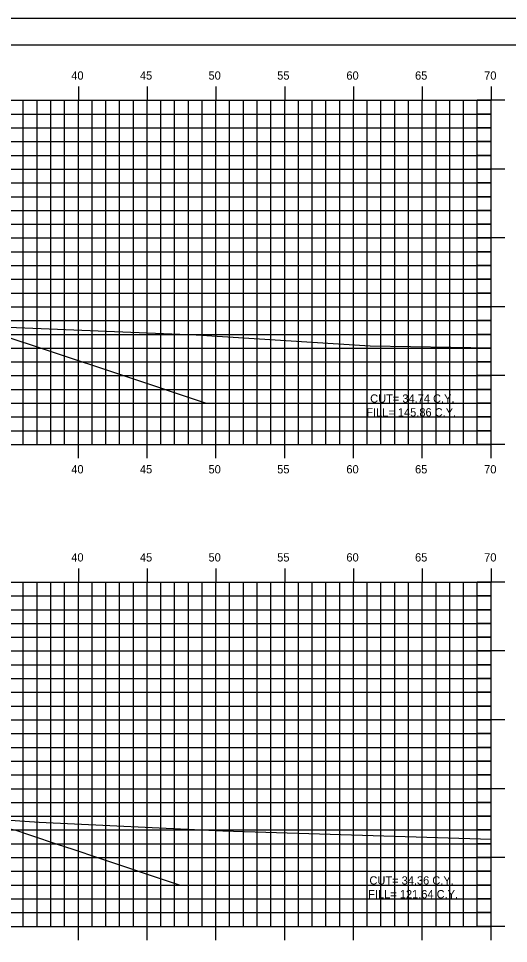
# Model space of a CAD drawing. Extents: x 1170543 to 1177585, y 609599 to 610623.
# Drawn here: x 1175836.2 to 1175871.9, y 609641.6 to 609708.8 of the extents above; entities that cross this region are included whole.
import ezdxf

# ---------------------------------------------------------------- set-up
doc = ezdxf.new("R2010")
doc.units = 0
for name, color, linetype in [('BORDER', 7, 'Continuous'), ('D_Roadway_Centerline_Text', 7, 'Continuous'), ('D_Roadway_Edge_Pavement', 7, 'Continuous'), ('H_V ANNOTATION', 7, 'Continuous'), ('MAJOR', 7, 'Continuous'), ('MINOR', 7, 'Continuous'), ('PLOT BOUNDARY', 7, 'Continuous'), ('S_Roadway_Centerline', 7, 'Continuous')]:
    doc.layers.add(name, color=color, linetype=linetype)

msp = doc.modelspace()

# ---------------------------------------------------------------- linework, layer by layer
at = {"layer": 'BORDER'}
msp.add_line((1175885.583, 609706.872), (1175725.583, 609706.872), dxfattribs=at)
at = {"layer": 'D_Roadway_Edge_Pavement'}
for points in [[(1175831.415, 609686.695), (1175834.869, 609685.872), (1175835.47, 609685.672), (1175837.87, 609684.872), (1175838.471, 609684.672), (1175840.872, 609683.872), (1175841.472, 609683.672), (1175843.874, 609682.872), (1175849.877, 609680.872), (1175870.583, 609680.872)], [(1175830.368, 609650.953), (1175835.978, 609649.872), (1175837.246, 609649.45), (1175838.981, 609648.872), (1175840.258, 609648.447), (1175841.984, 609647.872), (1175847.99, 609645.872), (1175870.583, 609645.872)]]:
    msp.add_lwpolyline(points, dxfattribs=at)
at = {"layer": 'MAJOR'}
for p, q in [((1175840.583, 609703.874), (1175840.583, 609702.872)), ((1175845.583, 609703.874), (1175845.583, 609702.872)), ((1175850.583, 609703.874), (1175850.583, 609702.872)), ((1175855.583, 609703.874), (1175855.583, 609702.872)), ((1175860.583, 609703.874), (1175860.583, 609702.872)), ((1175865.583, 609703.874), (1175865.583, 609702.872)), ((1175870.583, 609703.874), (1175870.583, 609702.872)), ((1175730.583, 609702.872), (1175870.583, 609702.872)), ((1175730.583, 609702.872), (1175870.583, 609702.872)), ((1175840.583, 609677.872), (1175840.583, 609702.872)), ((1175845.583, 609677.872), (1175845.583, 609702.872)), ((1175850.583, 609677.872), (1175850.583, 609702.872)), ((1175855.583, 609677.872), (1175855.583, 609702.872)), ((1175860.583, 609677.872), (1175860.583, 609702.872)), ((1175865.583, 609677.872), (1175865.583, 609702.872)), ((1175871.585, 609702.872), (1175869.581, 609702.872)), ((1175870.583, 609677.872), (1175870.583, 609702.872)), ((1175870.583, 609677.872), (1175870.583, 609702.872)), ((1175730.583, 609697.872), (1175870.583, 609697.872)), ((1175871.585, 609697.872), (1175869.581, 609697.872)), ((1175730.583, 609692.872), (1175870.583, 609692.872)), ((1175871.585, 609692.872), (1175869.581, 609692.872)), ((1175730.583, 609687.872), (1175870.583, 609687.872)), ((1175871.585, 609687.872), (1175869.581, 609687.872)), ((1175730.583, 609682.872), (1175870.583, 609682.872)), ((1175871.585, 609682.872), (1175869.581, 609682.872)), ((1175730.583, 609677.872), (1175870.583, 609677.872)), ((1175730.583, 609677.872), (1175870.583, 609677.872)), ((1175840.583, 609676.87), (1175840.583, 609677.872)), ((1175845.583, 609676.87), (1175845.583, 609677.872)), ((1175850.583, 609676.87), (1175850.583, 609677.872)), ((1175855.583, 609676.87), (1175855.583, 609677.872)), ((1175860.583, 609676.87), (1175860.583, 609677.872)), ((1175865.583, 609676.87), (1175865.583, 609677.872)), ((1175871.585, 609677.872), (1175869.581, 609677.872)), ((1175870.583, 609676.87), (1175870.583, 609677.872)), ((1175840.583, 609668.874), (1175840.583, 609667.872)), ((1175845.583, 609668.874), (1175845.583, 609667.872)), ((1175850.583, 609668.874), (1175850.583, 609667.872)), ((1175855.583, 609668.874), (1175855.583, 609667.872)), ((1175860.583, 609668.874), (1175860.583, 609667.872)), ((1175865.583, 609668.874), (1175865.583, 609667.872)), ((1175870.583, 609668.874), (1175870.583, 609667.872)), ((1175730.583, 609667.872), (1175870.583, 609667.872)), ((1175730.583, 609667.872), (1175870.583, 609667.872)), ((1175840.583, 609642.872), (1175840.583, 609667.872)), ((1175845.583, 609642.872), (1175845.583, 609667.872)), ((1175850.583, 609642.872), (1175850.583, 609667.872)), ((1175855.583, 609642.872), (1175855.583, 609667.872)), ((1175860.583, 609642.872), (1175860.583, 609667.872)), ((1175865.583, 609642.872), (1175865.583, 609667.872)), ((1175871.585, 609667.872), (1175869.581, 609667.872)), ((1175870.583, 609642.872), (1175870.583, 609667.872)), ((1175870.583, 609642.872), (1175870.583, 609667.872)), ((1175730.583, 609662.872), (1175870.583, 609662.872)), ((1175871.585, 609662.872), (1175869.581, 609662.872)), ((1175730.583, 609657.872), (1175870.583, 609657.872)), ((1175871.585, 609657.872), (1175869.581, 609657.872)), ((1175730.583, 609652.872), (1175870.583, 609652.872)), ((1175871.585, 609652.872), (1175869.581, 609652.872)), ((1175730.583, 609647.872), (1175870.583, 609647.872)), ((1175871.585, 609647.872), (1175869.581, 609647.872)), ((1175730.583, 609642.872), (1175870.583, 609642.872)), ((1175730.583, 609642.872), (1175870.583, 609642.872)), ((1175840.583, 609641.87), (1175840.583, 609642.872)), ((1175845.583, 609641.87), (1175845.583, 609642.872)), ((1175850.583, 609641.87), (1175850.583, 609642.872)), ((1175855.583, 609641.87), (1175855.583, 609642.872)), ((1175860.583, 609641.87), (1175860.583, 609642.872)), ((1175865.583, 609641.87), (1175865.583, 609642.872)), ((1175871.585, 609642.872), (1175869.581, 609642.872)), ((1175870.583, 609641.87), (1175870.583, 609642.872))]:
    msp.add_line(p, q, dxfattribs=at)
at = {"layer": 'MINOR'}
for p, q in [((1175836.583, 609677.872), (1175836.583, 609702.872)), ((1175837.583, 609677.872), (1175837.583, 609702.872)), ((1175838.583, 609677.872), (1175838.583, 609702.872)), ((1175839.583, 609677.872), (1175839.583, 609702.872)), ((1175841.583, 609677.872), (1175841.583, 609702.872)), ((1175842.583, 609677.872), (1175842.583, 609702.872)), ((1175843.583, 609677.872), (1175843.583, 609702.872)), ((1175844.583, 609677.872), (1175844.583, 609702.872)), ((1175846.583, 609677.872), (1175846.583, 609702.872)), ((1175847.583, 609677.872), (1175847.583, 609702.872)), ((1175848.583, 609677.872), (1175848.583, 609702.872)), ((1175849.583, 609677.872), (1175849.583, 609702.872)), ((1175851.583, 609677.872), (1175851.583, 609702.872)), ((1175852.583, 609677.872), (1175852.583, 609702.872)), ((1175853.583, 609677.872), (1175853.583, 609702.872)), ((1175854.583, 609677.872), (1175854.583, 609702.872)), ((1175856.583, 609677.872), (1175856.583, 609702.872)), ((1175857.583, 609677.872), (1175857.583, 609702.872)), ((1175858.583, 609677.872), (1175858.583, 609702.872)), ((1175859.583, 609677.872), (1175859.583, 609702.872)), ((1175861.583, 609677.872), (1175861.583, 609702.872)), ((1175862.583, 609677.872), (1175862.583, 609702.872)), ((1175863.583, 609677.872), (1175863.583, 609702.872)), ((1175864.583, 609677.872), (1175864.583, 609702.872)), ((1175866.583, 609677.872), (1175866.583, 609702.872)), ((1175867.583, 609677.872), (1175867.583, 609702.872)), ((1175868.583, 609677.872), (1175868.583, 609702.872)), ((1175869.583, 609677.872), (1175869.583, 609702.872)), ((1175730.583, 609701.872), (1175870.583, 609701.872)), ((1175870.583, 609701.872), (1175869.581, 609701.872)), ((1175730.583, 609700.872), (1175870.583, 609700.872)), ((1175870.583, 609700.872), (1175869.581, 609700.872)), ((1175730.583, 609699.872), (1175870.583, 609699.872)), ((1175870.583, 609699.872), (1175869.581, 609699.872)), ((1175730.583, 609698.872), (1175870.583, 609698.872)), ((1175870.583, 609698.872), (1175869.581, 609698.872)), ((1175730.583, 609696.872), (1175870.583, 609696.872)), ((1175870.583, 609696.872), (1175869.581, 609696.872)), ((1175730.583, 609695.872), (1175870.583, 609695.872)), ((1175870.583, 609695.872), (1175869.581, 609695.872)), ((1175730.583, 609694.872), (1175870.583, 609694.872)), ((1175870.583, 609694.872), (1175869.581, 609694.872)), ((1175730.583, 609693.872), (1175870.583, 609693.872)), ((1175870.583, 609693.872), (1175869.581, 609693.872)), ((1175730.583, 609691.872), (1175870.583, 609691.872)), ((1175870.583, 609691.872), (1175869.581, 609691.872)), ((1175730.583, 609690.872), (1175870.583, 609690.872)), ((1175870.583, 609690.872), (1175869.581, 609690.872)), ((1175730.583, 609689.872), (1175870.583, 609689.872)), ((1175870.583, 609689.872), (1175869.581, 609689.872)), ((1175730.583, 609688.872), (1175870.583, 609688.872)), ((1175870.583, 609688.872), (1175869.581, 609688.872)), ((1175730.583, 609686.872), (1175870.583, 609686.872)), ((1175870.583, 609686.872), (1175869.581, 609686.872)), ((1175730.583, 609685.872), (1175870.583, 609685.872)), ((1175870.583, 609685.872), (1175869.581, 609685.872)), ((1175730.583, 609684.872), (1175870.583, 609684.872)), ((1175870.583, 609684.872), (1175869.581, 609684.872)), ((1175730.583, 609683.872), (1175870.583, 609683.872)), ((1175870.583, 609683.872), (1175869.581, 609683.872)), ((1175730.583, 609681.872), (1175870.583, 609681.872)), ((1175870.583, 609681.872), (1175869.581, 609681.872)), ((1175730.583, 609680.872), (1175870.583, 609680.872)), ((1175870.583, 609680.872), (1175869.581, 609680.872)), ((1175730.583, 609679.872), (1175870.583, 609679.872)), ((1175870.583, 609679.872), (1175869.581, 609679.872)), ((1175730.583, 609678.872), (1175870.583, 609678.872)), ((1175870.583, 609678.872), (1175869.581, 609678.872)), ((1175836.583, 609642.872), (1175836.583, 609667.872)), ((1175837.583, 609642.872), (1175837.583, 609667.872)), ((1175838.583, 609642.872), (1175838.583, 609667.872)), ((1175839.583, 609642.872), (1175839.583, 609667.872)), ((1175841.583, 609642.872), (1175841.583, 609667.872)), ((1175842.583, 609642.872), (1175842.583, 609667.872)), ((1175843.583, 609642.872), (1175843.583, 609667.872)), ((1175844.583, 609642.872), (1175844.583, 609667.872)), ((1175846.583, 609642.872), (1175846.583, 609667.872)), ((1175847.583, 609642.872), (1175847.583, 609667.872)), ((1175848.583, 609642.872), (1175848.583, 609667.872)), ((1175849.583, 609642.872), (1175849.583, 609667.872)), ((1175851.583, 609642.872), (1175851.583, 609667.872)), ((1175852.583, 609642.872), (1175852.583, 609667.872)), ((1175853.583, 609642.872), (1175853.583, 609667.872)), ((1175854.583, 609642.872), (1175854.583, 609667.872)), ((1175856.583, 609642.872), (1175856.583, 609667.872)), ((1175857.583, 609642.872), (1175857.583, 609667.872)), ((1175858.583, 609642.872), (1175858.583, 609667.872)), ((1175859.583, 609642.872), (1175859.583, 609667.872)), ((1175861.583, 609642.872), (1175861.583, 609667.872)), ((1175862.583, 609642.872), (1175862.583, 609667.872)), ((1175863.583, 609642.872), (1175863.583, 609667.872)), ((1175864.583, 609642.872), (1175864.583, 609667.872)), ((1175866.583, 609642.872), (1175866.583, 609667.872)), ((1175867.583, 609642.872), (1175867.583, 609667.872)), ((1175868.583, 609642.872), (1175868.583, 609667.872)), ((1175869.583, 609642.872), (1175869.583, 609667.872)), ((1175730.583, 609666.872), (1175870.583, 609666.872)), ((1175870.583, 609666.872), (1175869.581, 609666.872)), ((1175730.583, 609665.872), (1175870.583, 609665.872)), ((1175870.583, 609665.872), (1175869.581, 609665.872)), ((1175730.583, 609664.872), (1175870.583, 609664.872)), ((1175870.583, 609664.872), (1175869.581, 609664.872)), ((1175730.583, 609663.872), (1175870.583, 609663.872)), ((1175870.583, 609663.872), (1175869.581, 609663.872)), ((1175730.583, 609661.872), (1175870.583, 609661.872)), ((1175870.583, 609661.872), (1175869.581, 609661.872)), ((1175730.583, 609660.872), (1175870.583, 609660.872)), ((1175870.583, 609660.872), (1175869.581, 609660.872)), ((1175730.583, 609659.872), (1175870.583, 609659.872)), ((1175870.583, 609659.872), (1175869.581, 609659.872)), ((1175730.583, 609658.872), (1175870.583, 609658.872)), ((1175870.583, 609658.872), (1175869.581, 609658.872)), ((1175730.583, 609656.872), (1175870.583, 609656.872)), ((1175870.583, 609656.872), (1175869.581, 609656.872)), ((1175730.583, 609655.872), (1175870.583, 609655.872)), ((1175870.583, 609655.872), (1175869.581, 609655.872)), ((1175730.583, 609654.872), (1175870.583, 609654.872)), ((1175870.583, 609654.872), (1175869.581, 609654.872)), ((1175730.583, 609653.872), (1175870.583, 609653.872)), ((1175870.583, 609653.872), (1175869.581, 609653.872)), ((1175730.583, 609651.872), (1175870.583, 609651.872)), ((1175870.583, 609651.872), (1175869.581, 609651.872)), ((1175730.583, 609650.872), (1175870.583, 609650.872)), ((1175870.583, 609650.872), (1175869.581, 609650.872)), ((1175730.583, 609649.872), (1175870.583, 609649.872)), ((1175870.583, 609649.872), (1175869.581, 609649.872)), ((1175730.583, 609648.872), (1175870.583, 609648.872)), ((1175870.583, 609648.872), (1175869.581, 609648.872)), ((1175730.583, 609646.872), (1175870.583, 609646.872)), ((1175870.583, 609646.872), (1175869.581, 609646.872)), ((1175730.583, 609645.872), (1175870.583, 609645.872)), ((1175870.583, 609645.872), (1175869.581, 609645.872)), ((1175730.583, 609644.872), (1175870.583, 609644.872)), ((1175870.583, 609644.872), (1175869.581, 609644.872)), ((1175730.583, 609643.872), (1175870.583, 609643.872)), ((1175870.583, 609643.872), (1175869.581, 609643.872))]:
    msp.add_line(p, q, dxfattribs=at)
at = {"layer": 'PLOT BOUNDARY'}
msp.add_lwpolyline([(1175717.49, 609598.813), (1175887.49, 609598.813), (1175887.49, 609708.813), (1175717.49, 609708.813)], close=True, dxfattribs=at)
at = {"layer": 'S_Roadway_Centerline'}
for points in [[(1175772.531, 609694.049), (1175776.22, 609693.954), (1175777.579, 609693.919), (1175781.368, 609693.765), (1175781.445, 609693.762), (1175781.835, 609693.751), (1175785.681, 609693.649), (1175786.914, 609693.609), (1175788.104, 609693.574), (1175788.352, 609693.515), (1175789.355, 609693.243), (1175789.937, 609693.076), (1175792.687, 609692.514), (1175802.476, 609689.845), (1175808.926, 609688.076), (1175817.846, 609687.673), (1175835.498, 609686.401), (1175849.143, 609685.837), (1175861.799, 609685.044), (1175870.583, 609684.889)], [(1175770.459, 609658.349), (1175774.474, 609658.207), (1175775.524, 609658.177), (1175775.968, 609658.072), (1175777.158, 609657.8), (1175777.668, 609657.678), (1175777.877, 609657.64), (1175778.153, 609657.585), (1175778.359, 609657.548), (1175778.754, 609657.475), (1175779.857, 609657.287), (1175788.937, 609655.408), (1175789.039, 609655.389), (1175802.408, 609652.655), (1175806.955, 609652.329), (1175826.495, 609651.211), (1175837.733, 609650.448), (1175851.088, 609649.815), (1175870.583, 609649.202)]]:
    msp.add_lwpolyline(points, dxfattribs=at)

# ---------------------------------------------------------------- texts
at = {"layer": 'D_Roadway_Centerline_Text'}
for s, p in [('CUT= 34.74 C.Y.', (1175861.797, 609680.908)), ('FILL= 145.86 C.Y.', (1175861.514, 609679.906)), ('CUT= 34.36 C.Y.', (1175861.743, 609645.908)), ('FILL= 121.64 C.Y.', (1175861.653, 609644.906))]:
    msp.add_text(s, height=0.6, dxfattribs=at).set_placement(p)
at = {"layer": 'H_V ANNOTATION'}
for s, p in [('40', (1175840.069, 609704.372)), ('45', (1175845.061, 609704.372)), ('50', (1175850.047, 609704.372)), ('55', (1175855.039, 609704.372)), ('60', (1175860.069, 609704.372)), ('65', (1175865.061, 609704.372)), ('70', (1175870.085, 609704.372)), ('40', (1175840.069, 609675.772)), ('45', (1175845.061, 609675.772)), ('50', (1175850.047, 609675.772)), ('55', (1175855.039, 609675.772)), ('60', (1175860.069, 609675.772)), ('65', (1175865.061, 609675.772)), ('70', (1175870.085, 609675.772)), ('40', (1175840.069, 609669.372)), ('45', (1175845.061, 609669.372)), ('50', (1175850.047, 609669.372)), ('55', (1175855.039, 609669.372)), ('60', (1175860.069, 609669.372)), ('65', (1175865.061, 609669.372)), ('70', (1175870.085, 609669.372))]:
    msp.add_text(s, height=0.6, dxfattribs=at).set_placement(p)

doc.saveas('drawing.dxf')
